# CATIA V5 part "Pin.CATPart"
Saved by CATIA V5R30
Part number: Pin
Bounding box of the stored display mesh (mm): x -15 to 15, y -15 to 15, z -50 to 0
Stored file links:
  D:\PROJECTS\CATIA V56R 2020\Resources\Parts File\c12_catia_v5_6r2020_prt\c12_catia_v5-6r2020 figr_12-30\Pin.CATPart
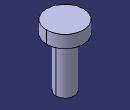
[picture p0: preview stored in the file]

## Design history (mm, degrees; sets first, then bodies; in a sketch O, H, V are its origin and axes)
Body1 (main body)
  Sketch1 on xy-plane, origin (0, 0, 0), H (1, 0, 0), V (0, 1, 0)
    circle A1 centre (0, 0) radius 15
    circle A2 centre (0, 0) radius 7.5
    radius A2 = 7.5
    radius A1 = 15
  MultiPad1: profile Sketch1, domains (length -50; length -10)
